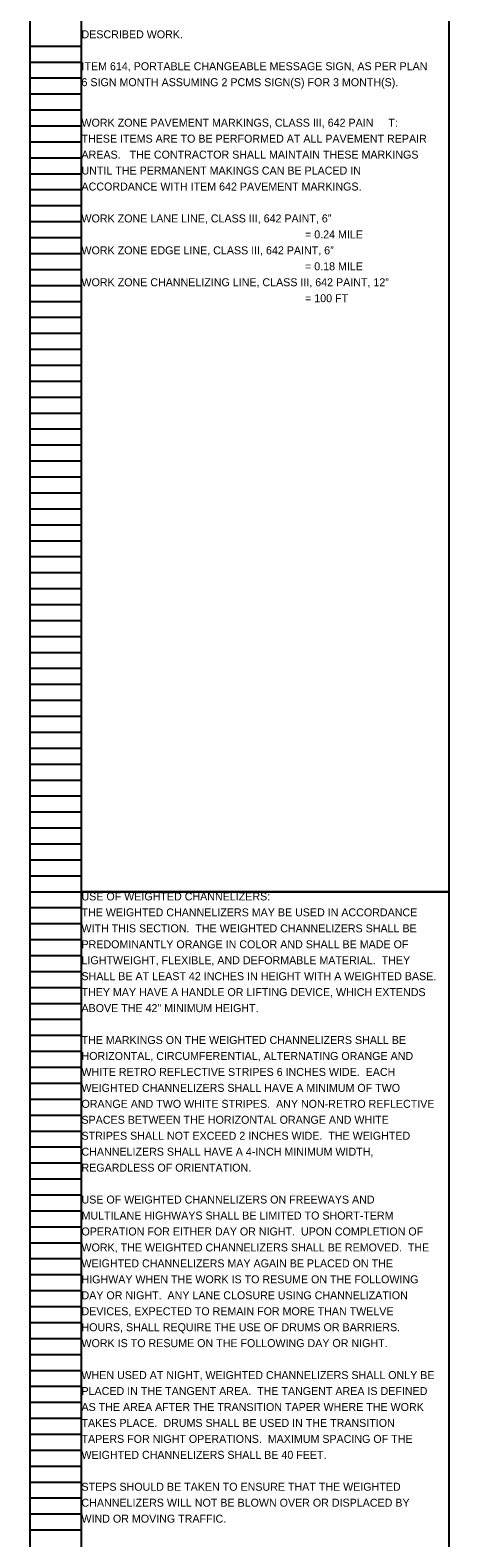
# Model space of a CAD drawing. Extents: x 16463 to 16500, y 5400 to 5823.
# Drawn here: x 16463.05 to 16470.39, y 5691.17 to 5717.63 of the extents above; entities that cross this region are included whole.
import ezdxf

# ---------------------------------------------------------------- set-up
doc = ezdxf.new("R2010")
doc.units = 0
for name, color, linetype in [('Default', 7, 'Continuous'), ('SC_Scratch1', 7, 'Continuous'), ('SH_Data', 7, 'Continuous')]:
    doc.layers.add(name, color=color, linetype=linetype)

msp = doc.modelspace()

# ---------------------------------------------------------------- linework, layer by layer
at = {"layer": 'SC_Scratch1'}
for points in [[(16463.949, 5722.672), (16470.389, 5722.672), (16470.389, 5702.512), (16463.949, 5702.512)], [(16463.949, 5702.512), (16470.389, 5702.512), (16470.389, 5682.352), (16463.949, 5682.352)]]:
    msp.add_lwpolyline(points, close=True, dxfattribs=at)
at = {"layer": 'SH_Data'}
for p, q in [((16463.049, 5702.512), (16463.049, 5722.672)), ((16463.949, 5702.512), (16463.949, 5722.672)), ((16463.049, 5717.352), (16463.949, 5717.352)), ((16463.049, 5717.072), (16463.949, 5717.072)), ((16463.049, 5716.792), (16463.949, 5716.792)), ((16463.049, 5716.512), (16463.949, 5716.512)), ((16463.049, 5716.232), (16463.949, 5716.232)), ((16463.049, 5715.952), (16463.949, 5715.952)), ((16463.049, 5715.672), (16463.949, 5715.672)), ((16463.049, 5715.392), (16463.949, 5715.392)), ((16463.049, 5715.112), (16463.949, 5715.112)), ((16463.049, 5714.832), (16463.949, 5714.832)), ((16463.049, 5714.552), (16463.949, 5714.552)), ((16463.049, 5714.272), (16463.949, 5714.272)), ((16463.049, 5713.992), (16463.949, 5713.992)), ((16463.049, 5713.712), (16463.949, 5713.712)), ((16463.049, 5713.432), (16463.949, 5713.432)), ((16463.049, 5713.152), (16463.949, 5713.152)), ((16463.049, 5712.872), (16463.949, 5712.872)), ((16463.049, 5712.592), (16463.949, 5712.592)), ((16463.049, 5712.312), (16463.949, 5712.312)), ((16463.049, 5712.032), (16463.949, 5712.032)), ((16463.049, 5711.752), (16463.949, 5711.752)), ((16463.049, 5711.472), (16463.949, 5711.472)), ((16463.049, 5711.192), (16463.949, 5711.192)), ((16463.049, 5710.912), (16463.949, 5710.912)), ((16463.049, 5710.632), (16463.949, 5710.632)), ((16463.049, 5710.352), (16463.949, 5710.352)), ((16463.049, 5710.072), (16463.949, 5710.072)), ((16463.049, 5709.792), (16463.949, 5709.792)), ((16463.049, 5709.512), (16463.949, 5709.512)), ((16463.049, 5709.232), (16463.949, 5709.232)), ((16463.049, 5708.952), (16463.949, 5708.952)), ((16463.049, 5708.672), (16463.949, 5708.672)), ((16463.049, 5708.392), (16463.949, 5708.392)), ((16463.049, 5708.112), (16463.949, 5708.112)), ((16463.049, 5707.832), (16463.949, 5707.832)), ((16463.049, 5707.552), (16463.949, 5707.552)), ((16463.049, 5707.272), (16463.949, 5707.272)), ((16463.049, 5706.992), (16463.949, 5706.992)), ((16463.049, 5706.712), (16463.949, 5706.712)), ((16463.049, 5706.432), (16463.949, 5706.432)), ((16463.049, 5706.152), (16463.949, 5706.152)), ((16463.049, 5705.872), (16463.949, 5705.872)), ((16463.049, 5705.592), (16463.949, 5705.592)), ((16463.049, 5705.312), (16463.949, 5705.312)), ((16463.049, 5705.032), (16463.949, 5705.032)), ((16463.049, 5704.752), (16463.949, 5704.752)), ((16463.049, 5704.472), (16463.949, 5704.472)), ((16463.049, 5704.192), (16463.949, 5704.192)), ((16463.049, 5703.912), (16463.949, 5703.912)), ((16463.049, 5703.632), (16463.949, 5703.632)), ((16463.049, 5703.352), (16463.949, 5703.352)), ((16463.049, 5703.072), (16463.949, 5703.072)), ((16463.049, 5702.792), (16463.949, 5702.792)), ((16463.049, 5682.352), (16463.049, 5702.512)), ((16463.049, 5702.512), (16463.949, 5702.512)), ((16463.049, 5702.512), (16463.949, 5702.512)), ((16463.949, 5682.352), (16463.949, 5702.512)), ((16463.049, 5702.232), (16463.949, 5702.232)), ((16463.049, 5701.952), (16463.949, 5701.952)), ((16463.049, 5701.672), (16463.949, 5701.672)), ((16463.049, 5701.392), (16463.949, 5701.392)), ((16463.049, 5701.112), (16463.949, 5701.112)), ((16463.049, 5700.832), (16463.949, 5700.832)), ((16463.049, 5700.552), (16463.949, 5700.552)), ((16463.049, 5700.272), (16463.949, 5700.272)), ((16463.049, 5699.992), (16463.949, 5699.992)), ((16463.049, 5699.712), (16463.949, 5699.712)), ((16463.049, 5699.432), (16463.949, 5699.432)), ((16463.049, 5699.152), (16463.949, 5699.152)), ((16463.049, 5698.872), (16463.949, 5698.872)), ((16463.049, 5698.592), (16463.949, 5698.592)), ((16463.049, 5698.312), (16463.949, 5698.312)), ((16463.049, 5698.032), (16463.949, 5698.032)), ((16463.049, 5697.752), (16463.949, 5697.752)), ((16463.049, 5697.472), (16463.949, 5697.472)), ((16463.049, 5697.192), (16463.949, 5697.192)), ((16463.049, 5696.912), (16463.949, 5696.912)), ((16463.049, 5696.632), (16463.949, 5696.632)), ((16463.049, 5696.352), (16463.949, 5696.352)), ((16463.049, 5696.072), (16463.949, 5696.072)), ((16463.049, 5695.792), (16463.949, 5695.792)), ((16463.049, 5695.512), (16463.949, 5695.512)), ((16463.049, 5695.232), (16463.949, 5695.232)), ((16463.049, 5694.952), (16463.949, 5694.952)), ((16463.049, 5694.672), (16463.949, 5694.672)), ((16463.049, 5694.392), (16463.949, 5694.392)), ((16463.049, 5694.112), (16463.949, 5694.112)), ((16463.049, 5693.832), (16463.949, 5693.832)), ((16463.049, 5693.552), (16463.949, 5693.552)), ((16463.049, 5693.272), (16463.949, 5693.272)), ((16463.049, 5692.992), (16463.949, 5692.992)), ((16463.049, 5692.712), (16463.949, 5692.712)), ((16463.049, 5692.432), (16463.949, 5692.432)), ((16463.049, 5692.152), (16463.949, 5692.152)), ((16463.049, 5691.872), (16463.949, 5691.872)), ((16463.049, 5691.592), (16463.949, 5691.592)), ((16463.049, 5691.312), (16463.949, 5691.312))]:
    msp.add_line(p, q, dxfattribs=at)

# ---------------------------------------------------------------- texts
at = {"layer": 'Default'}
for s, p in [('DESCRIBED WORK. ', (16463.949, 5717.488)), ('ITEM 614, PORTABLE CHANGEABLE MESSAGE SIGN, AS PER PLAN ', (16463.949, 5716.928)), ('6 SIGN MONTH ASSUMING 2 PCMS SIGN(S) FOR 3 MONTH(S).', (16463.949, 5716.648)), ('WORK ZONE PAVEMENT MARKINGS, CLASS III, 642 PAIN', (16463.949, 5715.937)), ('T:', (16469.329, 5715.937)), ('THESE ITEMS ARE TO BE PERFORMED AT ALL PAVEMENT REPAIR ', (16463.949, 5715.657)), ('AREAS.   THE CONTRACTOR SHALL MAINTAIN THESE MARKINGS ', (16463.949, 5715.377)), ('UNTIL THE PERMANENT MAKINGS CAN BE PLACED IN ', (16463.949, 5715.097)), ('ACCORDANCE WITH ITEM 642 PAVEMENT MARKINGS. ', (16463.949, 5714.817)), ('WORK ZONE LANE LINE, CLASS III, 642 PAINT, 6”         ', (16463.949, 5714.257)), ('= 0.24 MILE', (16467.869, 5713.977)), ('WORK ZONE EDGE LINE, CLASS III, 642 PAINT, 6”', (16463.949, 5713.697)), ('= 0.18 MILE', (16467.869, 5713.417)), ('WORK ZONE CHANNELIZING LINE, CLASS III, 642 PAINT, 12”  ', (16463.949, 5713.137)), ('= 100 FT', (16467.869, 5712.857)), ('USE OF WEIGHTED CHANNELIZERS:', (16463.949, 5702.359)), ('THE WEIGHTED CHANNELIZERS MAY BE USED IN ACCORDANCE ', (16463.949, 5702.079)), ('WITH THIS SECTION.  THE WEIGHTED CHANNELIZERS SHALL BE ', (16463.949, 5701.799)), ('PREDOMINANTLY ORANGE IN COLOR AND SHALL BE MADE OF ', (16463.949, 5701.519)), ('LIGHTWEIGHT, FLEXIBLE, AND DEFORMABLE MATERIAL.  THEY ', (16463.949, 5701.239)), ('SHALL BE AT LEAST 42 INCHES IN HEIGHT WITH A WEIGHTED BASE.  ', (16463.949, 5700.959)), ('THEY MAY HAVE A HANDLE OR LIFTING DEVICE, WHICH EXTENDS ', (16463.949, 5700.679)), ('ABOVE THE 42" MINIMUM HEIGHT.', (16463.949, 5700.399)), ('THE MARKINGS ON THE WEIGHTED CHANNELIZERS SHALL BE ', (16463.949, 5699.839)), ('HORIZONTAL, CIRCUMFERENTIAL, ALTERNATING ORANGE AND ', (16463.949, 5699.559)), ('WHITE RETRO REFLECTIVE STRIPES 6 INCHES WIDE.  EACH ', (16463.949, 5699.279)), ('WEIGHTED CHANNELIZERS SHALL HAVE A MINIMUM OF TWO ', (16463.949, 5698.999)), ('ORANGE AND TWO WHITE STRIPES.  ANY NON-RETRO REFLECTIVE ', (16463.949, 5698.719)), ('SPACES BETWEEN THE HORIZONTAL ORANGE AND WHITE ', (16463.949, 5698.439)), ('STRIPES SHALL NOT EXCEED 2 INCHES WIDE.  THE WEIGHTED ', (16463.949, 5698.159)), ('CHANNELIZERS SHALL HAVE A 4-INCH MINIMUM WIDTH, ', (16463.949, 5697.879)), ('REGARDLESS OF ORIENTATION.', (16463.949, 5697.599)), ('USE OF WEIGHTED CHANNELIZERS ON FREEWAYS AND ', (16463.949, 5697.039)), ('MULTILANE HIGHWAYS SHALL BE LIMITED TO SHORT-TERM ', (16463.949, 5696.759)), ('OPERATION FOR EITHER DAY OR NIGHT.  UPON COMPLETION OF ', (16463.949, 5696.479)), ('WORK, THE WEIGHTED CHANNELIZERS SHALL BE REMOVED.  THE ', (16463.949, 5696.199)), ('WEIGHTED CHANNELIZERS MAY AGAIN BE PLACED ON THE ', (16463.949, 5695.919)), ('HIGHWAY WHEN THE WORK IS TO RESUME ON THE FOLLOWING ', (16463.949, 5695.639)), ('DAY OR NIGHT.  ANY LANE CLOSURE USING CHANNELIZATION ', (16463.949, 5695.359)), ('DEVICES, EXPECTED TO REMAIN FOR MORE THAN TWELVE ', (16463.949, 5695.079)), ('HOURS, SHALL REQUIRE THE USE OF DRUMS OR BARRIERS.  ', (16463.949, 5694.799)), ('WORK IS TO RESUME ON THE FOLLOWING DAY OR NIGHT.', (16463.949, 5694.519)), ('WHEN USED AT NIGHT, WEIGHTED CHANNELIZERS SHALL ONLY BE ', (16463.949, 5693.959)), ('PLACED IN THE TANGENT AREA.  THE TANGENT AREA IS DEFINED ', (16463.949, 5693.679)), ('AS THE AREA AFTER THE TRANSITION TAPER WHERE THE WORK ', (16463.949, 5693.399)), ('TAKES PLACE.  DRUMS SHALL BE USED IN THE TRANSITION ', (16463.949, 5693.119)), ('TAPERS FOR NIGHT OPERATIONS.  MAXIMUM SPACING OF THE ', (16463.949, 5692.839)), ('WEIGHTED CHANNELIZERS SHALL BE 40 FEET.', (16463.949, 5692.559)), ('STEPS SHOULD BE TAKEN TO ENSURE THAT THE WEIGHTED ', (16463.949, 5691.999)), ('CHANNELIZERS WILL NOT BE BLOWN OVER OR DISPLACED BY ', (16463.949, 5691.719)), ('WIND OR MOVING TRAFFIC.  ', (16463.949, 5691.439))]:
    msp.add_text(s, height=0.14, dxfattribs=at).set_placement(p)

doc.saveas('drawing.dxf')
